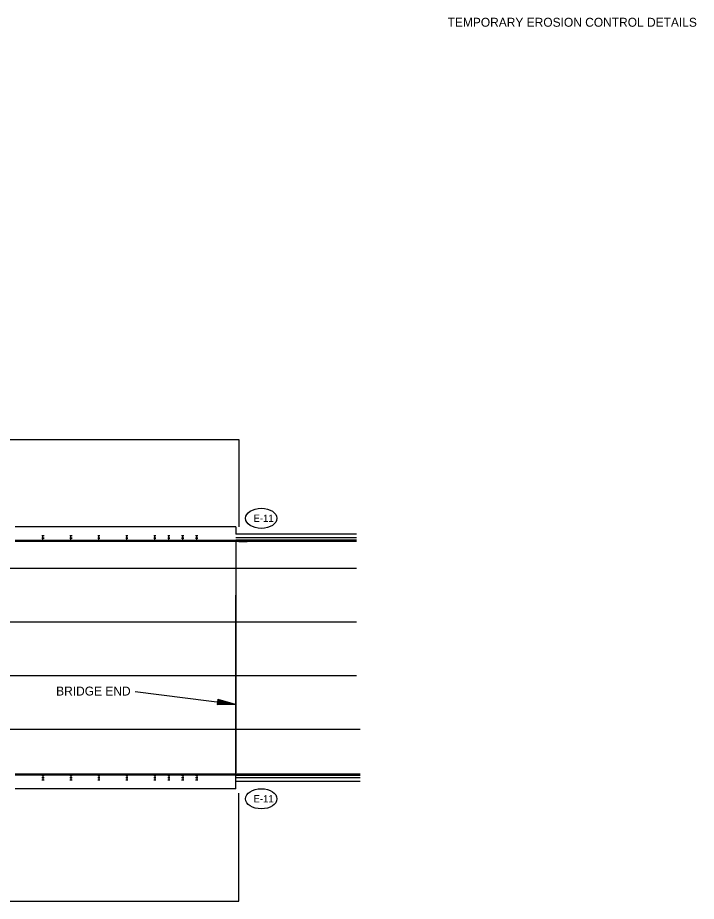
# Model space of a CAD drawing. Extents: x 1405295 to 1406670, y 2087573 to 2090763.
# Drawn here: x 1406215 to 1406670, y 2087970 to 2088563 of the extents above; entities that cross this region are included whole.
import ezdxf

# ---------------------------------------------------------------- set-up
doc = ezdxf.new("R2010")
doc.units = 0
for name, color, linetype in [('1', 7, 'Continuous'), ('22', 7, 'Continuous'), ('Default', 7, 'Continuous'), ('G-ANNO-TEXT', 7, 'Continuous')]:
    doc.layers.add(name, color=color, linetype=linetype)

msp = doc.modelspace()

# ---------------------------------------------------------------- linework, layer by layer
at = {"layer": '1'}
for centre in [(1406378.25, 2088227.12), (1406378.25, 2088038.91)]:
    msp.add_ellipse(centre, major_axis=(10.52, 0), ratio=0.638788, dxfattribs=at)
at = {"layer": '22'}
for points in [[(1405649.36, 2088280.09), (1406363.11, 2088280.09), (1406363.11, 2088221.33)], [(1405758.1, 2087970.09), (1406363.11, 2087970.09), (1406363.11, 2088042.57)]]:
    msp.add_lwpolyline(points, dxfattribs=at)
at = {"layer": 'Default'}
for p, q in [((1406361.31, 2088221.33), (1406213.1, 2088221.33)), ((1406231.1, 2088215.48), (1406231.85, 2088215.48)), ((1406231.85, 2088213.98), (1406231.85, 2088215.48)), ((1406231.85, 2088215.48), (1406232.6, 2088215.48)), ((1406249.85, 2088215.48), (1406250.6, 2088215.48)), ((1406250.6, 2088213.98), (1406250.6, 2088215.48)), ((1406250.6, 2088215.48), (1406251.35, 2088215.48)), ((1406268.6, 2088215.48), (1406269.35, 2088215.48)), ((1406269.35, 2088213.98), (1406269.35, 2088215.48)), ((1406269.35, 2088215.48), (1406270.1, 2088215.48)), ((1406287.35, 2088215.48), (1406288.1, 2088215.48)), ((1406288.1, 2088213.98), (1406288.1, 2088215.48)), ((1406288.1, 2088215.48), (1406288.85, 2088215.48)), ((1406306.1, 2088215.48), (1406306.85, 2088215.48)), ((1406306.85, 2088213.98), (1406306.85, 2088215.48)), ((1406306.85, 2088215.48), (1406307.6, 2088215.48)), ((1406315.49, 2088215.48), (1406316.24, 2088215.48)), ((1406316.24, 2088213.98), (1406316.24, 2088215.48)), ((1406316.24, 2088215.48), (1406316.99, 2088215.48)), ((1406324.86, 2088215.48), (1406325.61, 2088215.48)), ((1406325.61, 2088213.98), (1406325.61, 2088215.48)), ((1406325.61, 2088215.48), (1406326.36, 2088215.48)), ((1406334.25, 2088215.48), (1406335, 2088215.48)), ((1406335, 2088213.98), (1406335, 2088215.48)), ((1406335, 2088215.48), (1406335.75, 2088215.48)), ((1406361.31, 2088221.33), (1406361.31, 2088216.53)), ((1406442.16, 2088216.53), (1406361.31, 2088216.53)), ((1406363.11, 2088212.33), (1406213.1, 2088212.33)), ((1406363.11, 2088211.52), (1406213.1, 2088211.52)), ((1406364.01, 2088211.52), (1406215.8, 2088211.52)), ((1406231.1, 2088213.98), (1406231.85, 2088213.98)), ((1406231.1, 2088213.83), (1406231.85, 2088213.83)), ((1406231.1, 2088212.33), (1406231.85, 2088212.33)), ((1406231.85, 2088213.98), (1406232.6, 2088213.98)), ((1406231.85, 2088212.33), (1406231.85, 2088213.83)), ((1406231.85, 2088213.83), (1406232.6, 2088213.83)), ((1406231.85, 2088212.33), (1406232.6, 2088212.33)), ((1406249.85, 2088213.98), (1406250.6, 2088213.98)), ((1406249.85, 2088213.83), (1406250.6, 2088213.83)), ((1406249.85, 2088212.33), (1406250.6, 2088212.33)), ((1406250.6, 2088213.98), (1406251.35, 2088213.98)), ((1406250.6, 2088212.33), (1406250.6, 2088213.83)), ((1406250.6, 2088213.83), (1406251.35, 2088213.83)), ((1406250.6, 2088212.33), (1406251.35, 2088212.33)), ((1406268.6, 2088213.98), (1406269.35, 2088213.98)), ((1406268.6, 2088213.83), (1406269.35, 2088213.83)), ((1406268.6, 2088212.33), (1406269.35, 2088212.33)), ((1406269.35, 2088213.98), (1406270.1, 2088213.98)), ((1406269.35, 2088212.33), (1406269.35, 2088213.83)), ((1406269.35, 2088213.83), (1406270.1, 2088213.83)), ((1406269.35, 2088212.33), (1406270.1, 2088212.33)), ((1406287.35, 2088213.98), (1406288.1, 2088213.98)), ((1406287.35, 2088213.83), (1406288.1, 2088213.83)), ((1406287.35, 2088212.33), (1406288.1, 2088212.33)), ((1406288.1, 2088213.98), (1406288.85, 2088213.98)), ((1406288.1, 2088212.33), (1406288.1, 2088213.83)), ((1406288.1, 2088213.83), (1406288.85, 2088213.83)), ((1406288.1, 2088212.33), (1406288.85, 2088212.33)), ((1406306.1, 2088213.98), (1406306.85, 2088213.98)), ((1406306.1, 2088213.83), (1406306.85, 2088213.83)), ((1406306.1, 2088212.33), (1406306.85, 2088212.33)), ((1406306.85, 2088213.98), (1406307.6, 2088213.98)), ((1406306.85, 2088212.33), (1406306.85, 2088213.83)), ((1406306.85, 2088213.83), (1406307.6, 2088213.83)), ((1406306.85, 2088212.33), (1406307.6, 2088212.33)), ((1406315.49, 2088213.98), (1406316.24, 2088213.98)), ((1406315.49, 2088213.83), (1406316.24, 2088213.83)), ((1406315.49, 2088212.33), (1406316.24, 2088212.33)), ((1406316.24, 2088213.98), (1406316.99, 2088213.98)), ((1406316.24, 2088212.33), (1406316.24, 2088213.83)), ((1406316.24, 2088213.83), (1406316.99, 2088213.83)), ((1406316.24, 2088212.33), (1406316.99, 2088212.33)), ((1406324.86, 2088213.98), (1406325.61, 2088213.98)), ((1406324.86, 2088213.83), (1406325.61, 2088213.83)), ((1406324.86, 2088212.33), (1406325.61, 2088212.33)), ((1406325.61, 2088213.98), (1406326.36, 2088213.98)), ((1406325.61, 2088212.33), (1406325.61, 2088213.83)), ((1406325.61, 2088213.83), (1406326.36, 2088213.83)), ((1406325.61, 2088212.33), (1406326.36, 2088212.33)), ((1406334.25, 2088213.98), (1406335, 2088213.98)), ((1406334.25, 2088213.83), (1406335, 2088213.83)), ((1406334.25, 2088212.33), (1406335, 2088212.33)), ((1406335, 2088213.98), (1406335.75, 2088213.98)), ((1406335, 2088212.33), (1406335, 2088213.83)), ((1406335, 2088213.83), (1406335.75, 2088213.83)), ((1406335, 2088212.33), (1406335.75, 2088212.33)), ((1406442.16, 2088214.04), (1406361.31, 2088214.04)), ((1406442.16, 2088212.48), (1406361.31, 2088212.48)), ((1406442.16, 2088211.52), (1406361.31, 2088211.52)), ((1406361.31, 2088211.52), (1406361.31, 2088056.26)), ((1406363.11, 2088211.52), (1406363.11, 2088212.33)), ((1406363.11, 2088212.33), (1406368.81, 2088212.33)), ((1406363.11, 2088211.52), (1406368.81, 2088211.52)), ((1406368.81, 2088211.52), (1406368.81, 2088212.33)), ((1406442.16, 2088193.52), (1405372.03, 2088193.52)), ((1406361.31, 2088050.52), (1406361.31, 2088175.51)), ((1406442.16, 2088157.51), (1405373.91, 2088157.51)), ((1406442.16, 2088121.51), (1405373.91, 2088121.51)), ((1406293.71, 2088110.9), (1406360.74, 2088102.37)), ((1406349.07, 2088105.67), (1406348.62, 2088102.1)), ((1406348.68, 2088102.7), (1406356.69, 2088102.88)), ((1406348.71, 2088103), (1406354.71, 2088103.12)), ((1406348.77, 2088103.3), (1406352.7, 2088103.39)), ((1406348.8, 2088103.6), (1406350.72, 2088103.63)), ((1406348.86, 2088104.18), (1406350.72, 2088103.63)), ((1406348.92, 2088104.47), (1406352.7, 2088103.39)), ((1406348.95, 2088104.77), (1406354.71, 2088103.12)), ((1406348.98, 2088105.07), (1406356.69, 2088102.88)), ((1406349.01, 2088105.38), (1406358.76, 2088102.61)), ((1406349.07, 2088105.67), (1406360.74, 2088102.37)), ((1406348.62, 2088102.1), (1406360.74, 2088102.37)), ((1406348.65, 2088102.4), (1406358.76, 2088102.61)), ((1406444.65, 2088085.51), (1405372.03, 2088085.51)), ((1406363.11, 2088055.51), (1406213.1, 2088055.51)), ((1406444.65, 2088055.51), (1406361.31, 2088055.51)), ((1406363.11, 2088055.51), (1406363.11, 2088054.7)), ((1406363.11, 2088055.51), (1406368.81, 2088055.51)), ((1406368.81, 2088055.51), (1406368.81, 2088054.7)), ((1406363.11, 2088054.7), (1406213.1, 2088054.7)), ((1406231.1, 2088054.7), (1406231.85, 2088054.7)), ((1406231.1, 2088053.2), (1406231.85, 2088053.2)), ((1406231.1, 2088053.08), (1406231.85, 2088053.08)), ((1406231.1, 2088051.58), (1406231.85, 2088051.58)), ((1406231.85, 2088054.7), (1406232.6, 2088054.7)), ((1406231.85, 2088054.7), (1406231.85, 2088053.2)), ((1406231.85, 2088053.2), (1406232.6, 2088053.2)), ((1406231.85, 2088053.08), (1406232.6, 2088053.08)), ((1406231.85, 2088053.08), (1406231.85, 2088051.58)), ((1406231.85, 2088051.58), (1406232.6, 2088051.58)), ((1406249.85, 2088054.7), (1406250.6, 2088054.7)), ((1406249.85, 2088053.2), (1406250.6, 2088053.2)), ((1406249.85, 2088053.08), (1406250.6, 2088053.08)), ((1406249.85, 2088051.58), (1406250.6, 2088051.58)), ((1406250.6, 2088054.7), (1406251.35, 2088054.7)), ((1406250.6, 2088054.7), (1406250.6, 2088053.2)), ((1406250.6, 2088053.2), (1406251.35, 2088053.2)), ((1406250.6, 2088053.08), (1406251.35, 2088053.08)), ((1406250.6, 2088053.08), (1406250.6, 2088051.58)), ((1406250.6, 2088051.58), (1406251.35, 2088051.58)), ((1406268.6, 2088054.7), (1406269.35, 2088054.7)), ((1406268.6, 2088053.2), (1406269.35, 2088053.2)), ((1406268.6, 2088053.08), (1406269.35, 2088053.08)), ((1406268.6, 2088051.58), (1406269.35, 2088051.58)), ((1406269.35, 2088054.7), (1406270.1, 2088054.7)), ((1406269.35, 2088054.7), (1406269.35, 2088053.2)), ((1406269.35, 2088053.2), (1406270.1, 2088053.2)), ((1406269.35, 2088053.08), (1406270.1, 2088053.08)), ((1406269.35, 2088053.08), (1406269.35, 2088051.58)), ((1406269.35, 2088051.58), (1406270.1, 2088051.58)), ((1406287.35, 2088054.7), (1406288.1, 2088054.7)), ((1406287.35, 2088053.2), (1406288.1, 2088053.2)), ((1406287.35, 2088053.08), (1406288.1, 2088053.08)), ((1406287.35, 2088051.58), (1406288.1, 2088051.58)), ((1406288.1, 2088054.7), (1406288.85, 2088054.7)), ((1406288.1, 2088054.7), (1406288.1, 2088053.2)), ((1406288.1, 2088053.2), (1406288.85, 2088053.2)), ((1406288.1, 2088053.08), (1406288.85, 2088053.08)), ((1406288.1, 2088053.08), (1406288.1, 2088051.58)), ((1406288.1, 2088051.58), (1406288.85, 2088051.58)), ((1406306.1, 2088054.7), (1406306.85, 2088054.7)), ((1406306.1, 2088053.2), (1406306.85, 2088053.2)), ((1406306.1, 2088053.08), (1406306.85, 2088053.08)), ((1406306.1, 2088051.58), (1406306.85, 2088051.58)), ((1406306.85, 2088054.7), (1406307.6, 2088054.7)), ((1406306.85, 2088054.7), (1406306.85, 2088053.2)), ((1406306.85, 2088053.2), (1406307.6, 2088053.2)), ((1406306.85, 2088053.08), (1406307.6, 2088053.08)), ((1406306.85, 2088053.08), (1406306.85, 2088051.58)), ((1406306.85, 2088051.58), (1406307.6, 2088051.58)), ((1406315.49, 2088054.7), (1406316.24, 2088054.7)), ((1406315.49, 2088053.2), (1406316.24, 2088053.2)), ((1406315.49, 2088053.08), (1406316.24, 2088053.08)), ((1406315.49, 2088051.58), (1406316.24, 2088051.58)), ((1406316.24, 2088054.7), (1406316.99, 2088054.7)), ((1406316.24, 2088054.7), (1406316.24, 2088053.2)), ((1406316.24, 2088053.2), (1406316.99, 2088053.2)), ((1406316.24, 2088053.08), (1406316.99, 2088053.08)), ((1406316.24, 2088053.08), (1406316.24, 2088051.58)), ((1406316.24, 2088051.58), (1406316.99, 2088051.58)), ((1406324.85, 2088054.7), (1406325.6, 2088054.7)), ((1406324.85, 2088053.2), (1406325.6, 2088053.2)), ((1406324.85, 2088053.08), (1406325.6, 2088053.08)), ((1406324.85, 2088051.58), (1406325.6, 2088051.58)), ((1406325.6, 2088054.7), (1406326.35, 2088054.7)), ((1406325.6, 2088054.7), (1406325.6, 2088053.2)), ((1406325.6, 2088053.2), (1406326.35, 2088053.2)), ((1406325.6, 2088053.08), (1406326.35, 2088053.08)), ((1406325.6, 2088053.08), (1406325.6, 2088051.58)), ((1406325.6, 2088051.58), (1406326.35, 2088051.58)), ((1406334.25, 2088054.7), (1406335, 2088054.7)), ((1406334.25, 2088053.2), (1406335, 2088053.2)), ((1406334.25, 2088053.08), (1406335, 2088053.08)), ((1406334.25, 2088051.58), (1406335, 2088051.58)), ((1406335, 2088054.7), (1406335.75, 2088054.7)), ((1406335, 2088054.7), (1406335, 2088053.2)), ((1406335, 2088053.2), (1406335.75, 2088053.2)), ((1406335, 2088053.08), (1406335.75, 2088053.08)), ((1406335, 2088053.08), (1406335, 2088051.58)), ((1406335, 2088051.58), (1406335.75, 2088051.58)), ((1406444.65, 2088054.58), (1406361.31, 2088054.58)), ((1406444.65, 2088053.02), (1406361.31, 2088053.02)), ((1406444.65, 2088050.52), (1406361.31, 2088050.52)), ((1406361.31, 2088045.69), (1406361.31, 2088050.52)), ((1406363.11, 2088054.7), (1406368.81, 2088054.7)), ((1406361.31, 2088045.69), (1406213.26, 2088045.69))]:
    msp.add_line(p, q, dxfattribs=at)

# ---------------------------------------------------------------- texts
at = {"layer": '1'}
for p in [(1406373.05, 2088224.76), (1406373.05, 2088036.55)]:
    msp.add_text('E-11', height=4.8, rotation=359.99998, dxfattribs=at).set_placement(p)
at = {"layer": 'Default'}
msp.add_text('BRIDGE END', height=6, rotation=359.99995, dxfattribs=at).set_placement((1406240.7, 2088108.19))
at = {"layer": 'G-ANNO-TEXT'}
msp.add_text('TEMPORARY EROSION CONTROL DETAILS', height=6, dxfattribs=at).set_placement((1406503.24, 2088557.01))

doc.saveas('drawing.dxf')
